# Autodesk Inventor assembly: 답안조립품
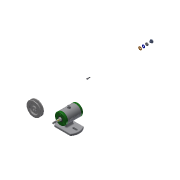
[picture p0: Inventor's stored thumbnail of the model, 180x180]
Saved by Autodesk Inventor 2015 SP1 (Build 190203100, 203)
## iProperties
Created: 2017-12
Part Number: 답안조립품
Document SubType Name: Assembly
Designer: C04
Author: C04
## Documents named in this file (14)
- C:\Users\C04\Desktop\471207V1022\답안조립품.iam
- C:\Users\C04\Desktop\471207V1022\1-본체.ipt
- C:\Users\C04\Desktop\471207V1022\2-베어링 15 x 32 x 9.ipt
- C:\Users\C04\Desktop\471207V1022\3-뒤커버.ipt
- C:\Users\C04\Desktop\471207V1022\4-앞커버.ipt
- C:\Users\C04\Desktop\471207V1022\5-오일 실 15 25 7.ipt
- C:\Users\C04\Desktop\471207V1022\6-볼트 M4 x 12.ipt
- C:\Users\C04\Desktop\471207V1022\7-축.ipt
- C:\Users\C04\Desktop\471207V1022\8-키 3 x 3 x 12.ipt
- C:\Users\C04\Desktop\471207V1022\9-V벨트풀리.ipt
- C:\Users\C04\Desktop\471207V1022\10-와셔 8x17.ipt
- C:\Users\C04\Desktop\471207V1022\11-스프링와셔 8.ipt
- C:\Users\C04\Desktop\471207V1022\12-너트 M 8.ipt
- C:\Users\C04\Desktop\471207V1022\13-고무캡.ipt
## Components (11 placed, 11 different names)
1. 1-본체:1
2. 3-뒤커버:1
3. 4-앞커버:1
4. 5-오일 실 15 25 7:1
5. 7-축:1 — 각도:1
6. 8-키 3 x 3 x 12:1 — 각도:1
7. 9-V벨트풀리:1
8. 10-와셔 8x17:1
9. 11-스프링와셔 8:1
10. 12-너트 M 8:1
11. 13-고무캡:1
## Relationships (1: Angle 1)
- 각도:1 [Angle]: 7-축:1 ↔ 8-키 3 x 3 x 12:1
